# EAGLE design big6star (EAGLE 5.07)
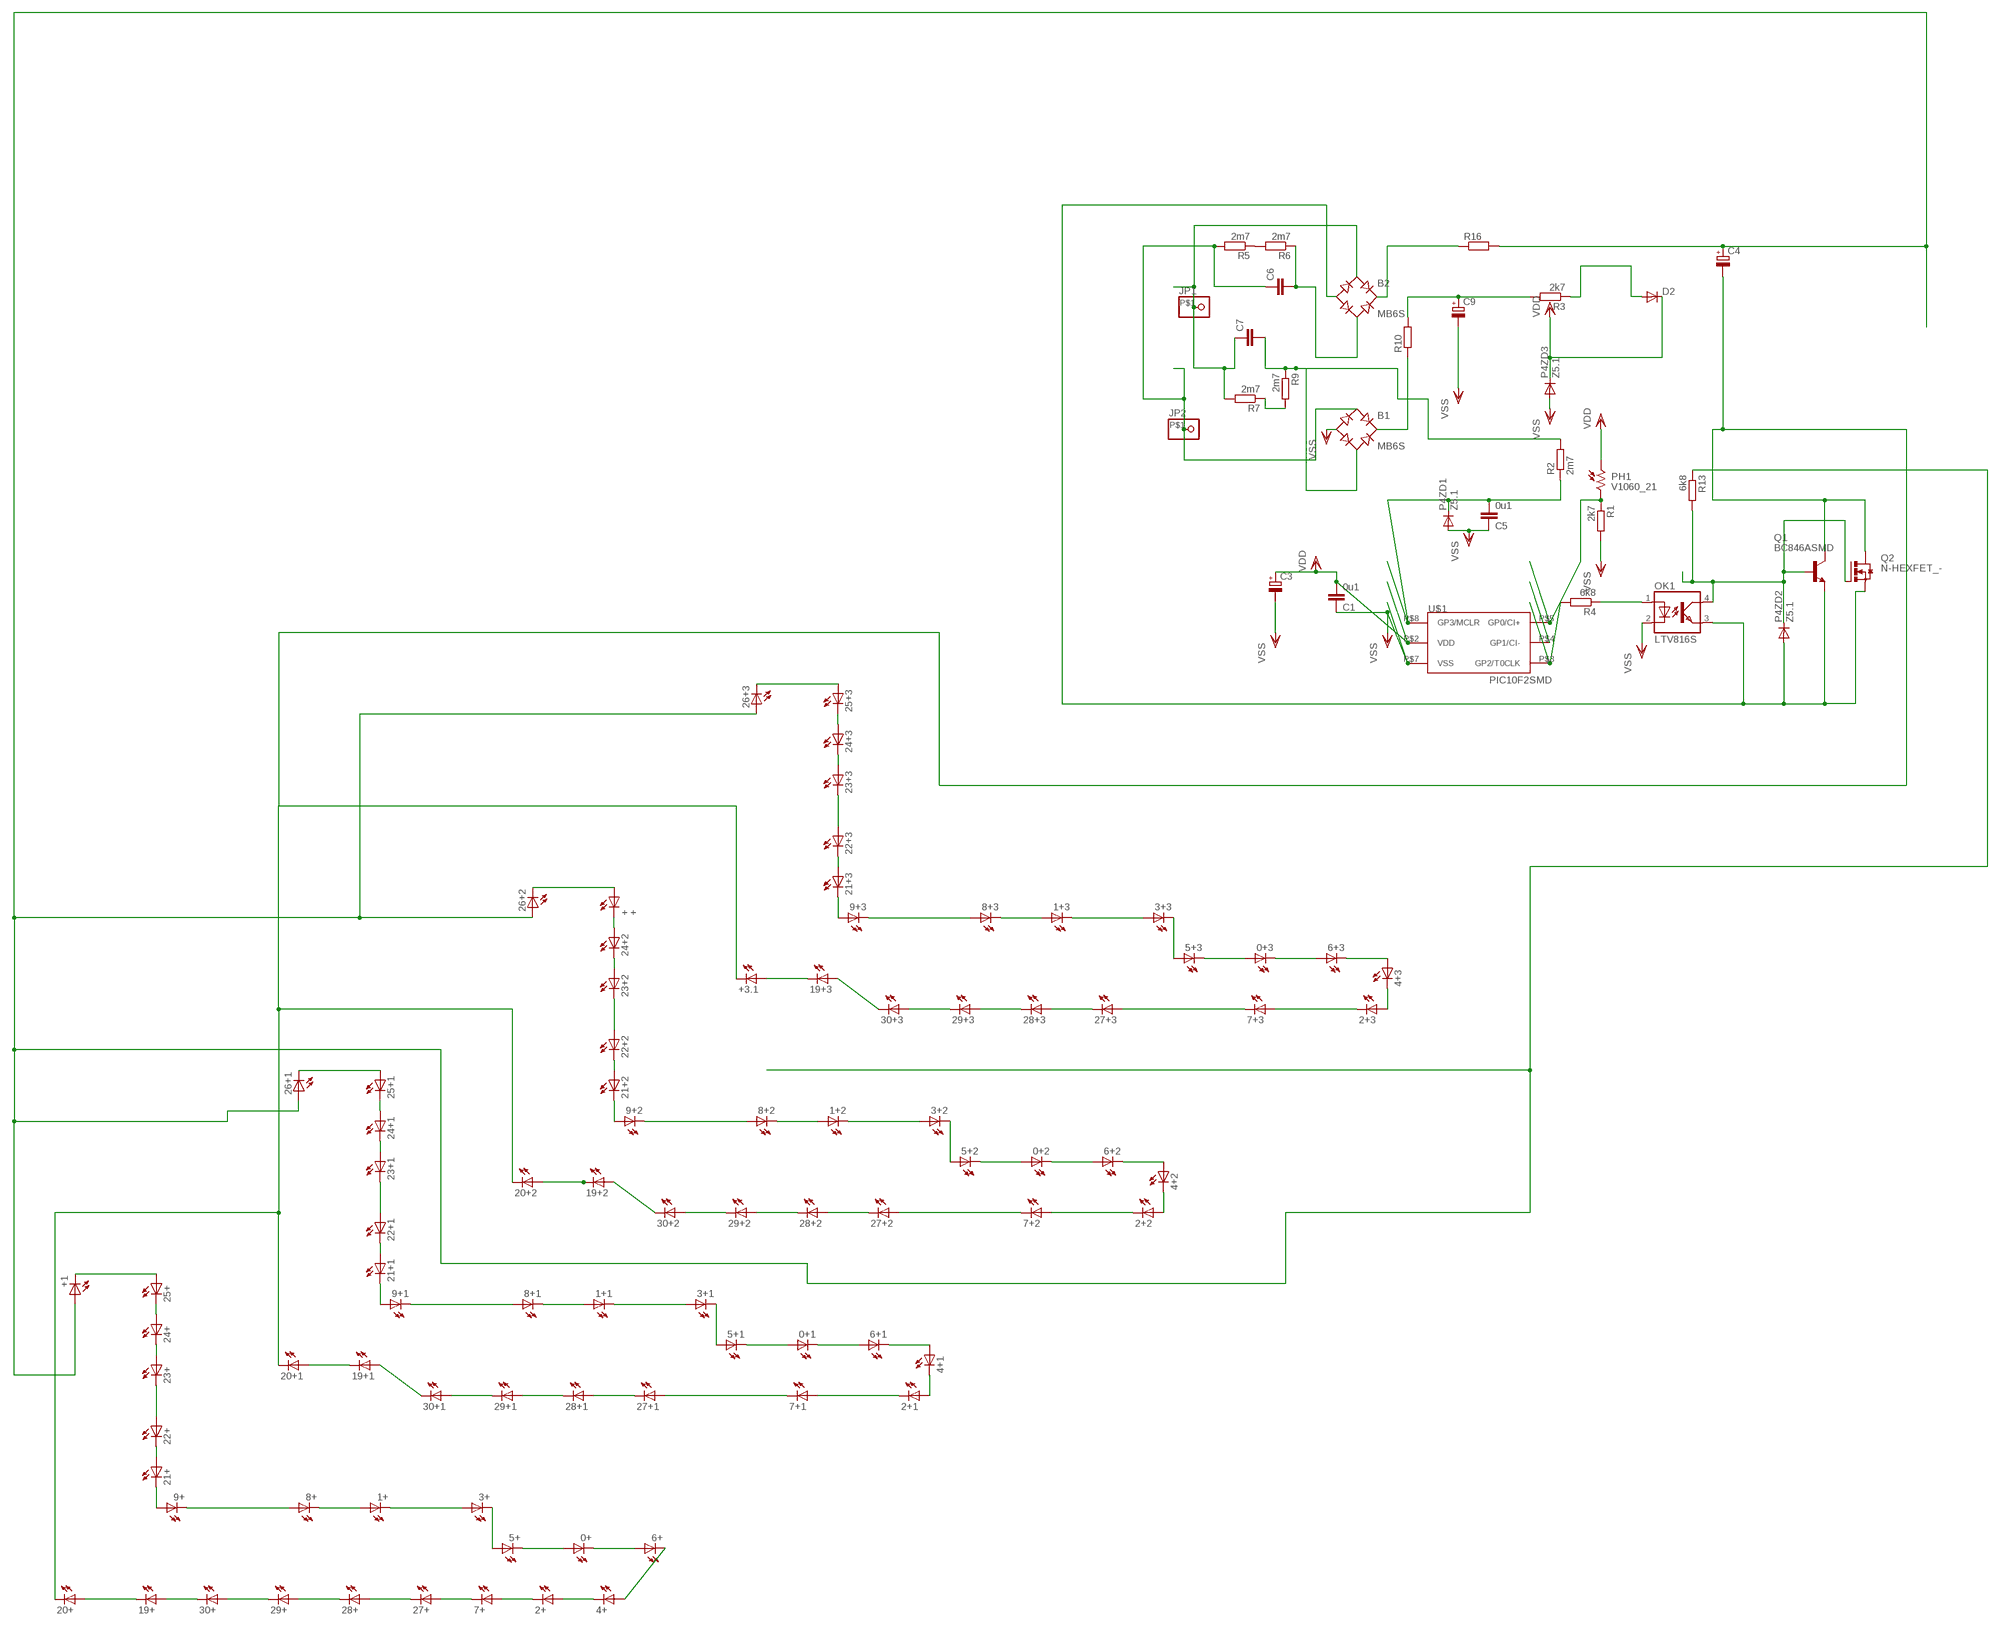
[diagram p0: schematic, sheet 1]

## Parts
0+  LED1210  [1210]
0+1  LED1210  [1210]
0+2  LED1210  [1210]
0+3  LED1210  [1210]
1+  LED1210  [1210]
1+1  LED1210  [1210]
1+2  LED1210  [1210]
1+3  LED1210  [1210]
2+  LED1210  [1210]
2+1  LED1210  [1210]
2+2  LED1210  [1210]
2+3  LED1210  [1210]
3+  LED1210  [1210]
3+1  LED1210  [1210]
3+2  LED1210  [1210]
3+3  LED1210  [1210]
4+  LED1210  [1210]
4+1  LED1210  [1210]
4+2  LED1210  [1210]
4+3  LED1210  [1210]
5+  LED1210  [1210]
5+1  LED1210  [1210]
5+2  LED1210  [1210]
5+3  LED1210  [1210]
6+  LED1210  [1210]
6+1  LED1210  [1210]
6+2  LED1210  [1210]
6+3  LED1210  [1210]
7+  LED1210  [1210]
7+1  LED1210  [1210]
7+2  LED1210  [1210]
7+3  LED1210  [1210]
8+  LED1210  [1210]
8+1  LED1210  [1210]
8+2  LED1210  [1210]
8+3  LED1210  [1210]
9+  LED1210  [1210]
9+1  LED1210  [1210]
9+2  LED1210  [1210]
9+3  LED1210  [1210]
19+  LED1210  [1210]
19+1  LED1210  [1210]
19+2  LED1210  [1210]
19+3  LED1210  [1210]
20+  LED1210  [1210]
20+1  LED1210  [1210]
20+2  LED1210  [1210]
21+  LED1210  [1210]
21+1  LED1210  [1210]
21+2  LED1210  [1210]
21+3  LED1210  [1210]
22+  LED1210  [1210]
22+1  LED1210  [1210]
22+2  LED1210  [1210]
22+3  LED1210  [1210]
23+  LED1210  [1210]
23+1  LED1210  [1210]
23+2  LED1210  [1210]
23+3  LED1210  [1210]
24+  LED1210  [1210]
24+1  LED1210  [1210]
24+2  LED1210  [1210]
24+3  LED1210  [1210]
25+  LED1210  [1210]
25+1  LED1210  [1210]
25+3  LED1210  [1210]
26+1  LED1210  [1210]
26+2  LED1210  [1210]
26+3  LED1210  [1210]
27+  LED1210  [1210]
27+1  LED1210  [1210]
27+2  LED1210  [1210]
27+3  LED1210  [1210]
28+  LED1210  [1210]
28+1  LED1210  [1210]
28+2  LED1210  [1210]
28+3  LED1210  [1210]
29+  LED1210  [1210]
29+1  LED1210  [1210]
29+2  LED1210  [1210]
29+3  LED1210  [1210]
30+  LED1210  [1210]
30+1  LED1210  [1210]
30+2  LED1210  [1210]
30+3  LED1210  [1210]
+  +  LED1210  [1210]
+1  LED1210  [1210]
+3.1  LED1210  [1210]
B1  MB6S  [SOIC-4]
B2  MB6S  [SOIC-4]
C1  0u1  C-EUC1206  [C1206]
C3  CPOL-EUD  [PANASONIC_D]
C4  CPOL-EUSANYO_SMD_F12  [SANYO-OSCON_SMD_F12]
C5  0u1  C-EUC1206  [C1206]
C6  C-EUSMD200  [SMD200]
C7  C-EUSMD100  [SMD100]
C9  CPOL-EUD  [PANASONIC_D]
D2  DIODE-MINIMELF  [MINIMELF]
JP1  PINHD-1X1SMD  [SMD1X1]
JP2  PINHD-1X1SMD  [SMD1X1]
OK1  LTV816S  [SMD4]
P4ZD1  Z5.1  DIODE-MINIMELF  [MINIMELF]
P4ZD2  Z5.1  DIODE-MINIMELF  [MINIMELF]
P4ZD3  Z5.1  DIODE-MINIMELF  [MINIMELF]
PH1  V1060_21  [TO-5_V10]
Q1  BC846ASMD  [SOT23]
Q2  N-HEXFET_-  [TO252]
R1  2k7  R-EU_R1206  [R1206]
R2  2m7  R-EU_R1206  [R1206]
R3  2k7  R-EU_R1206  [R1206]
R4  6k8  R-EU_R1206  [R1206]
R5  2m7  R-EU_R1210  [R1210]
R6  2m7  R-EU_R1210  [R1210]
R7  2m7  R-EU_R1210  [R1210]
R9  2m7  R-EU_R1210  [R1210]
R10  R-EU_SMD15  [SMDCARB15]
R13  6k8  R-EU_R1206  [R1206]
R16  R-EU_SMD15  [SMDCARB15]
U$1  PIC10F2SMD  [DIL8SMD]

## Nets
AC1: B1.~1(AC1) C6.P$1 JP2.P$1 R5.2
AC2: B2.~1(AC1) C7.P$1 JP1.P$1 R7.2
CBIG: B2.~2(AC2) C6.P$2 R6.1
CSMALL: B1.~2(AC2) C7.P$2 R2.2 R9.1
D+: 26+1.P$1(A) 26+2.P$1(A) 26+3.P$1(A) +1.P$1(A) C4.+ R13.1 R16.P$2
DR+: C9.+ R3.2 R10.P$2
MINUS: 20+1.P$2(C) 20+2.P$2(C) 20+.P$2(C) +3.1.P$2(C) C4.- Q1.3(C) Q2.3(D)
N$2: 19+.P$2(C) 20+.P$1(A)
N$4: 19+.P$1(A) 30+.P$2(C)
N$5: 19+1.P$1(A) 30+1.P$2(C)
N$6: 8+.P$1(A) 9+.P$2(C)
N$7: 29+.P$2(C) 30+.P$1(A)
N$8: 28+.P$2(C) 29+.P$1(A)
N$9: 27+.P$2(C) 28+.P$1(A)
N$10: 29+1.P$2(C) 30+1.P$1(A)
N$11: 28+1.P$2(C) 29+1.P$1(A)
N$12: 2+.P$2(C) 7+.P$1(A)
N$13: 7+.P$2(C) 27+.P$1(A)
N$14: 2+.P$1(A) 4+.P$2(C)
N$15: 4+.P$1(A) 6+.P$2(C)
N$16: 0+.P$2(C) 6+.P$1(A)
N$17: 0+.P$1(A) 5+.P$2(C)
N$18: 3+.P$2(C) 5+.P$1(A)
N$19: 1+.P$2(C) 3+.P$1(A)
N$20: 1+.P$1(A) 8+.P$2(C)
N$21: 27+1.P$2(C) 28+1.P$1(A)
N$22: 2+1.P$1(A) 4+1.P$2(C)
N$23: 9+.P$1(A) 21+.P$2(C)
N$24: 21+.P$1(A) 22+.P$2(C)
N$25: 22+.P$1(A) 23+.P$2(C)
N$26: 24+.P$1(A) 25+.P$2(C)
N$27: 25+.P$1(A) +1.P$2(C)
N$28: 23+.P$1(A) 24+.P$2(C)
N$29: 4+1.P$1(A) 6+1.P$2(C)
N$30: 0+1.P$2(C) 6+1.P$1(A)
N$31: 0+1.P$1(A) 5+1.P$2(C)
N$32: 3+1.P$2(C) 5+1.P$1(A)
N$33: 1+1.P$2(C) 3+1.P$1(A)
N$34: 1+1.P$1(A) 8+1.P$2(C)
N$35: 9+1.P$1(A) 21+1.P$2(C)
N$36: 21+1.P$1(A) 22+1.P$2(C)
N$37: 22+1.P$1(A) 23+1.P$2(C)
N$38: 25+1.P$1(A) 26+1.P$2(C)
N$39: 24+1.P$1(A) 25+1.P$2(C)
N$40: 23+1.P$1(A) 24+1.P$2(C)
N$41: 2+1.P$2(C) 7+1.P$1(A)
N$42: 7+1.P$2(C) 27+1.P$1(A)
N$43: 8+1.P$1(A) 9+1.P$2(C)
N$44: 19+1.P$2(C) 20+1.P$1(A)
N$45: 19+2.P$1(A) 30+2.P$2(C)
N$46: 29+2.P$2(C) 30+2.P$1(A)
N$47: 28+2.P$2(C) 29+2.P$1(A)
N$48: 27+2.P$2(C) 28+2.P$1(A)
N$49: 2+2.P$1(A) 4+2.P$2(C)
N$50: 4+2.P$1(A) 6+2.P$2(C)
N$51: 0+2.P$2(C) 6+2.P$1(A)
N$52: 0+2.P$1(A) 5+2.P$2(C)
N$53: 3+2.P$2(C) 5+2.P$1(A)
N$54: 1+2.P$2(C) 3+2.P$1(A)
N$55: 1+2.P$1(A) 8+2.P$2(C)
N$56: 9+2.P$1(A) 21+2.P$2(C)
N$57: 21+2.P$1(A) 22+2.P$2(C)
N$58: 22+2.P$1(A) 23+2.P$2(C)
N$59: 26+2.P$2(C) +.P$1(A)
N$60: 24+2.P$1(A) +.P$2(C)
N$61: 23+2.P$1(A) 24+2.P$2(C)
N$62: 2+2.P$2(C) 7+2.P$1(A)
N$63: 7+2.P$2(C) 27+2.P$1(A)
N$64: 8+2.P$1(A) 9+2.P$2(C)
N$65: 19+2.P$2(C) 20+2.P$1(A)
N$66: 19+3.P$1(A) 30+3.P$2(C)
N$67: 29+3.P$2(C) 30+3.P$1(A)
N$68: 28+3.P$2(C) 29+3.P$1(A)
N$69: 27+3.P$2(C) 28+3.P$1(A)
N$70: 2+3.P$1(A) 4+3.P$2(C)
N$71: 4+3.P$1(A) 6+3.P$2(C)
N$72: 0+3.P$2(C) 6+3.P$1(A)
N$73: 0+3.P$1(A) 5+3.P$2(C)
N$74: 3+3.P$2(C) 5+3.P$1(A)
N$75: 1+3.P$2(C) 3+3.P$1(A)
N$76: 1+3.P$1(A) 8+3.P$2(C)
N$77: 9+3.P$1(A) 21+3.P$2(C)
N$78: 21+3.P$1(A) 22+3.P$2(C)
N$79: 22+3.P$1(A) 23+3.P$2(C)
N$80: 25+3.P$1(A) 26+3.P$2(C)
N$81: 24+3.P$1(A) 25+3.P$2(C)
N$82: 23+3.P$1(A) 24+3.P$2(C)
N$83: 2+3.P$2(C) 7+3.P$1(A)
N$84: 7+3.P$2(C) 27+3.P$1(A)
N$85: 8+3.P$1(A) 9+3.P$2(C)
N$86: C5.2 P4ZD1.C R2.1 U$1.P$8(GP3/MCLR)
N$87: OK1.1(A) R4.1
N$88: PH1.2 R1.1 U$1.P$5(GP0/CI+)
N$89: R5.1 R6.2
N$90: R7.1 R9.2
N$91: B2.+ R16.P$1
N$92: D2.A R3.1
N$93: B2.- OK1.3(EMIT) P4ZD2.A Q1.2(E) Q2.2(S)
N$94: OK1.4(COL) P4ZD2.C Q1.1(B) Q2.1(G) R13.2
N$95: R4.2 U$1.P$3(GP2/T0CLK)
N$97: 19+3.P$2(C) +3.1.P$1(A)
N$102: U$1.P$4(GP1/CI-)
RECDR+: B1.+ R10.P$1
VDD: C1.2 C3.+ D2.C P4ZD3.C PH1.1 U$1.P$2(VDD)
VSS: B1.- C1.1 C3.- C5.1 C9.- OK1.2(C) P4ZD1.A P4ZD3.A R1.2 U$1.P$7(VSS)

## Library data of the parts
0+ 0+1-0+3 1+ 1+1-1+3 2+ 2+1-2+3 3+ 3+1-3+3 4+ 4+1-4+3 5+ 5+1-5+3 6+ 6+1-6+3 7+ 7+1-7+3 8+ 8+1-8+3 9+ 9+1-9+3 19+ 19+1-19+3 20+ 20+1 20+2 21+ 21+1-21+3 22+ 22+1-22+3 23+ 23+1-23+3 24+ 24+1-24+3 25+ 25+1 25+3 26+1-26+3 27+ 27+1-27+3 28+ 28+1-28+3 29+ 29+1-29+3 30+ 30+1-30+3 + +1 +3.1 = led(2):LED: LED
B1 B2 = rectifier:MB*S: Bridge Rectifier Source: http://www.fairchildsemi.com/ds/MB/MB6S.pdf
C1 C5-C7 = rcl:C-EU: CAPACITOR, European symbol
C3 C4 C9 = rcl-2:CPOL-EU: POLARIZED CAPACITOR, European symbol
D2 P4ZD1-P4ZD3 = diode:DIODE-: DIODE
JP1 JP2 = pinhead:PINHD-1X1: PIN HEADER
OK1 = optocoupler:LTV816: OPTO COUPLER Source: LITEON, LTV816.pdf
PH1 = photo-elements:?1060*: Sensor Street Light control
Q1 = transistor-npn:BC846*: NPN Transistor
Q2 = transistor-power:N-HEXFET_?-*: HEXFET® Power MOSFET
R1-R7 R9 R13 = rcl-2:R-EU_: RESISTOR, European symbol
R10 R16 = rcl:R-EU_: RESISTOR, European symbol
U$1 = microchip-5:PIC10F2*: uPC nW 0,25/0,5k Program Flash memory Comparator

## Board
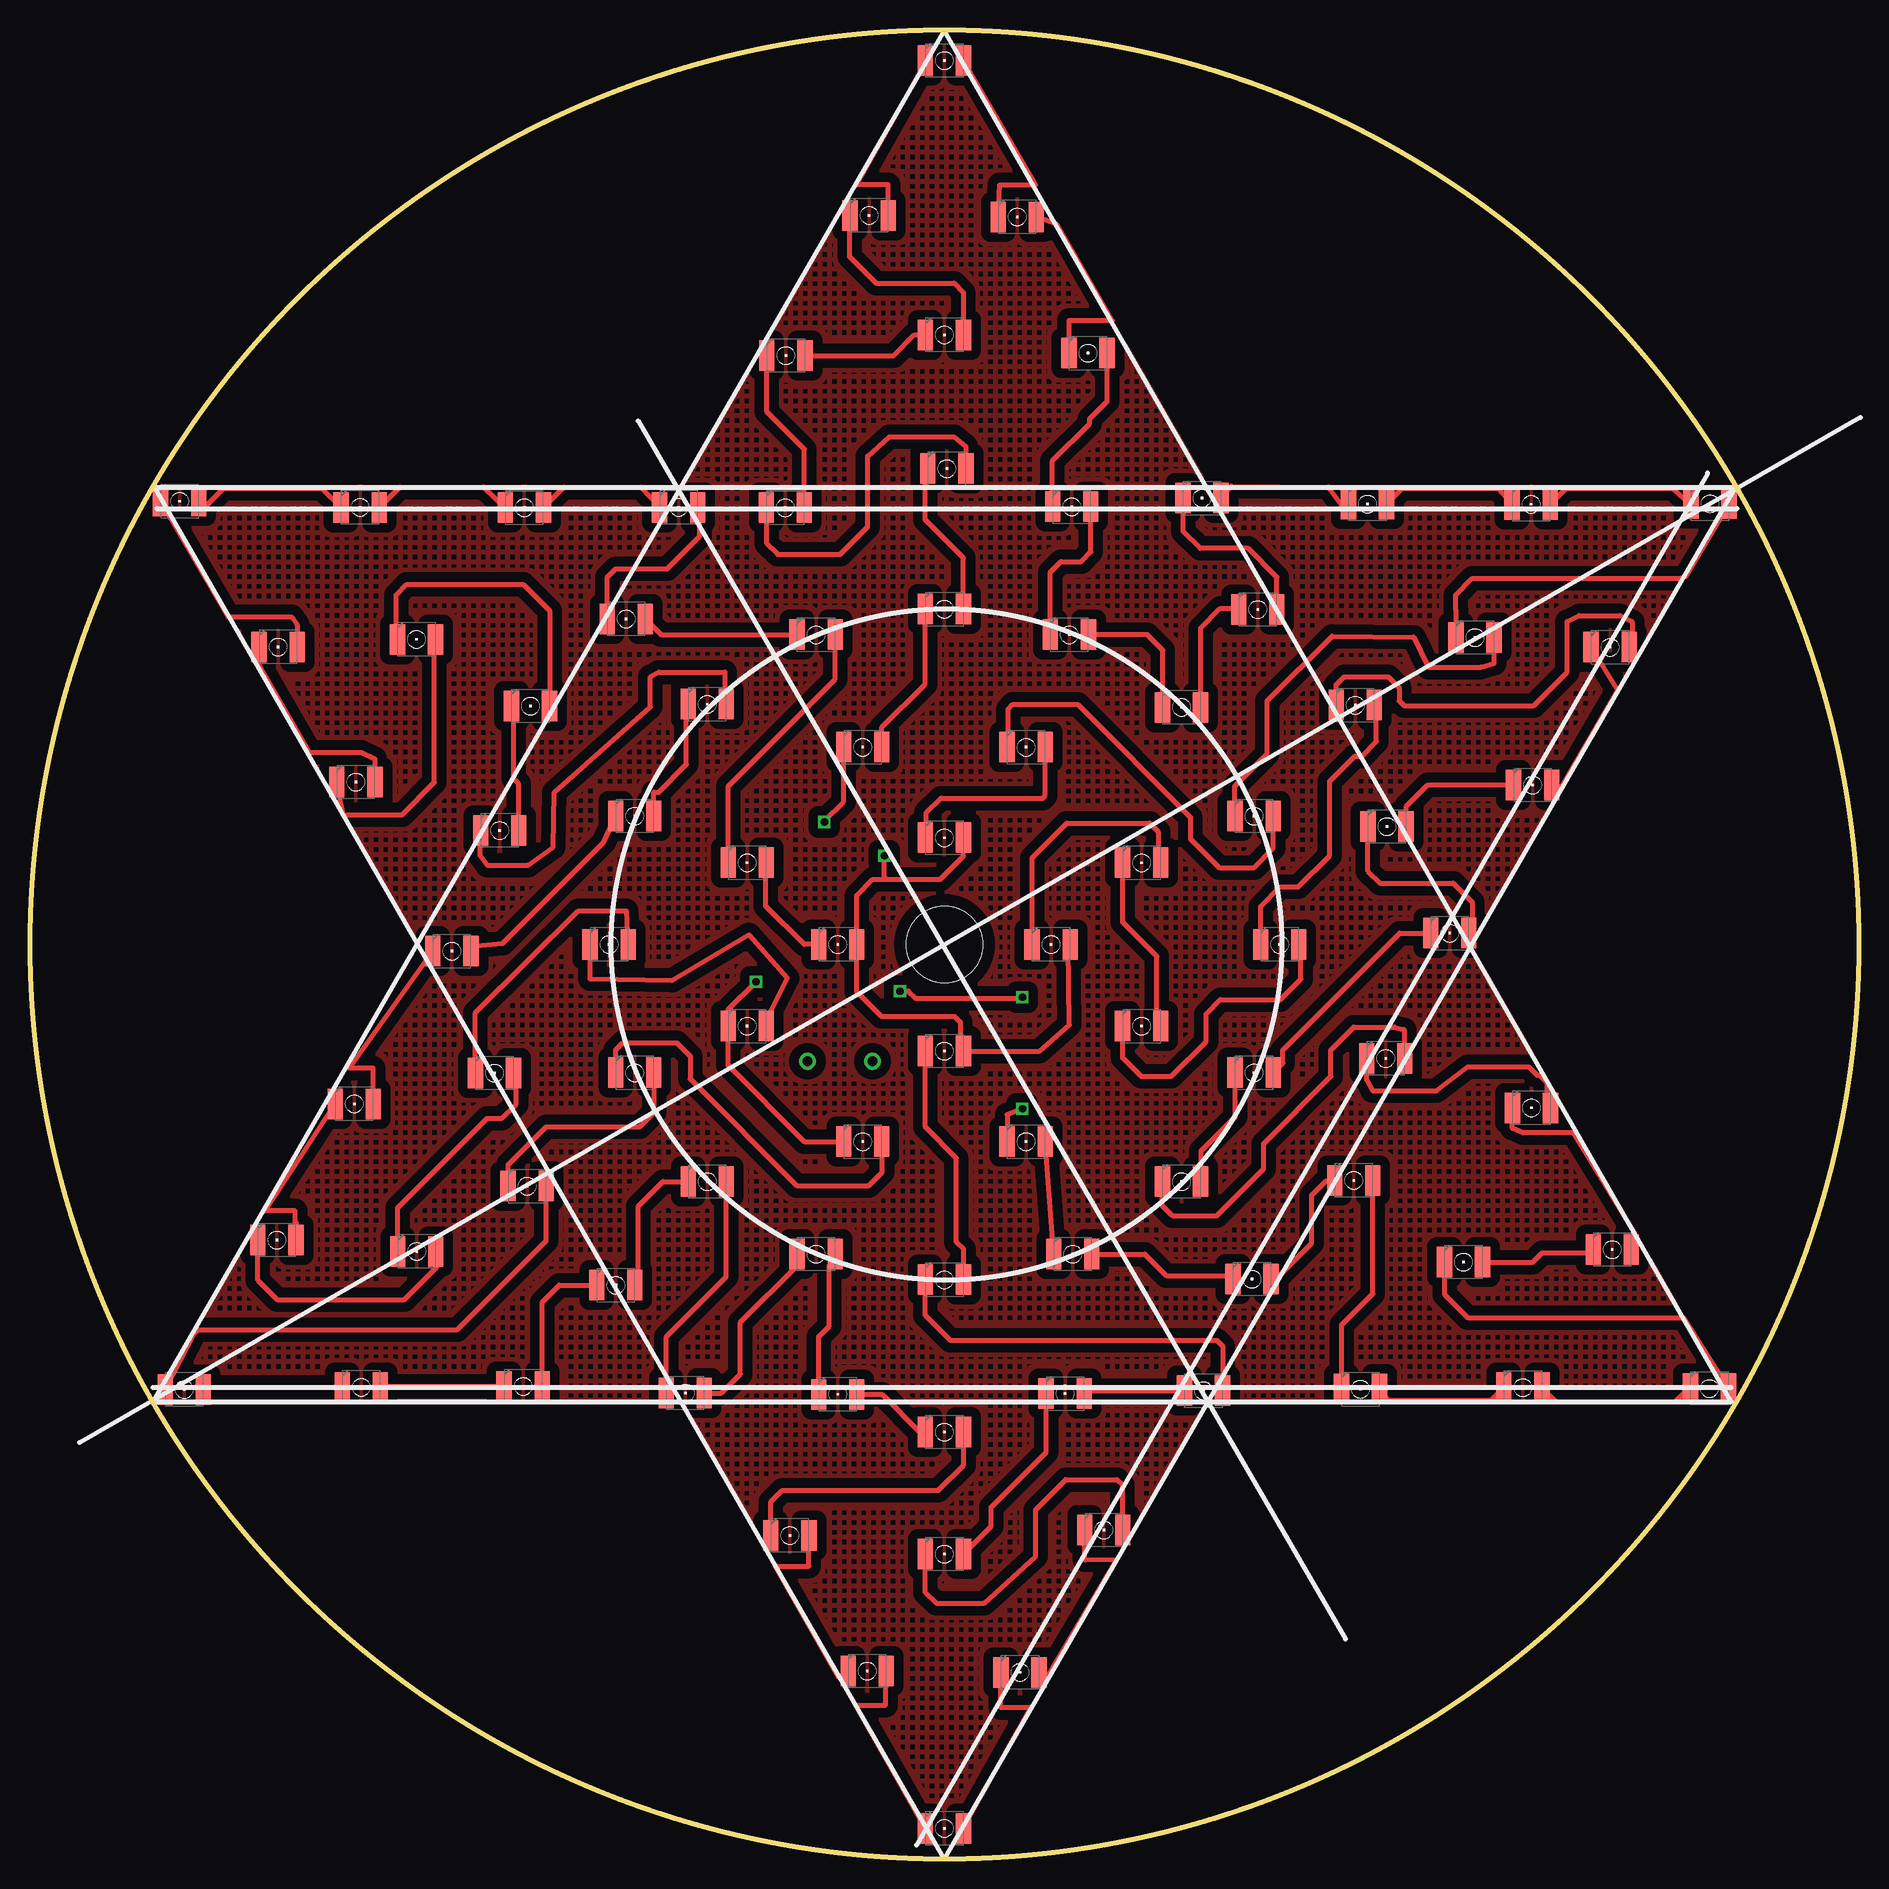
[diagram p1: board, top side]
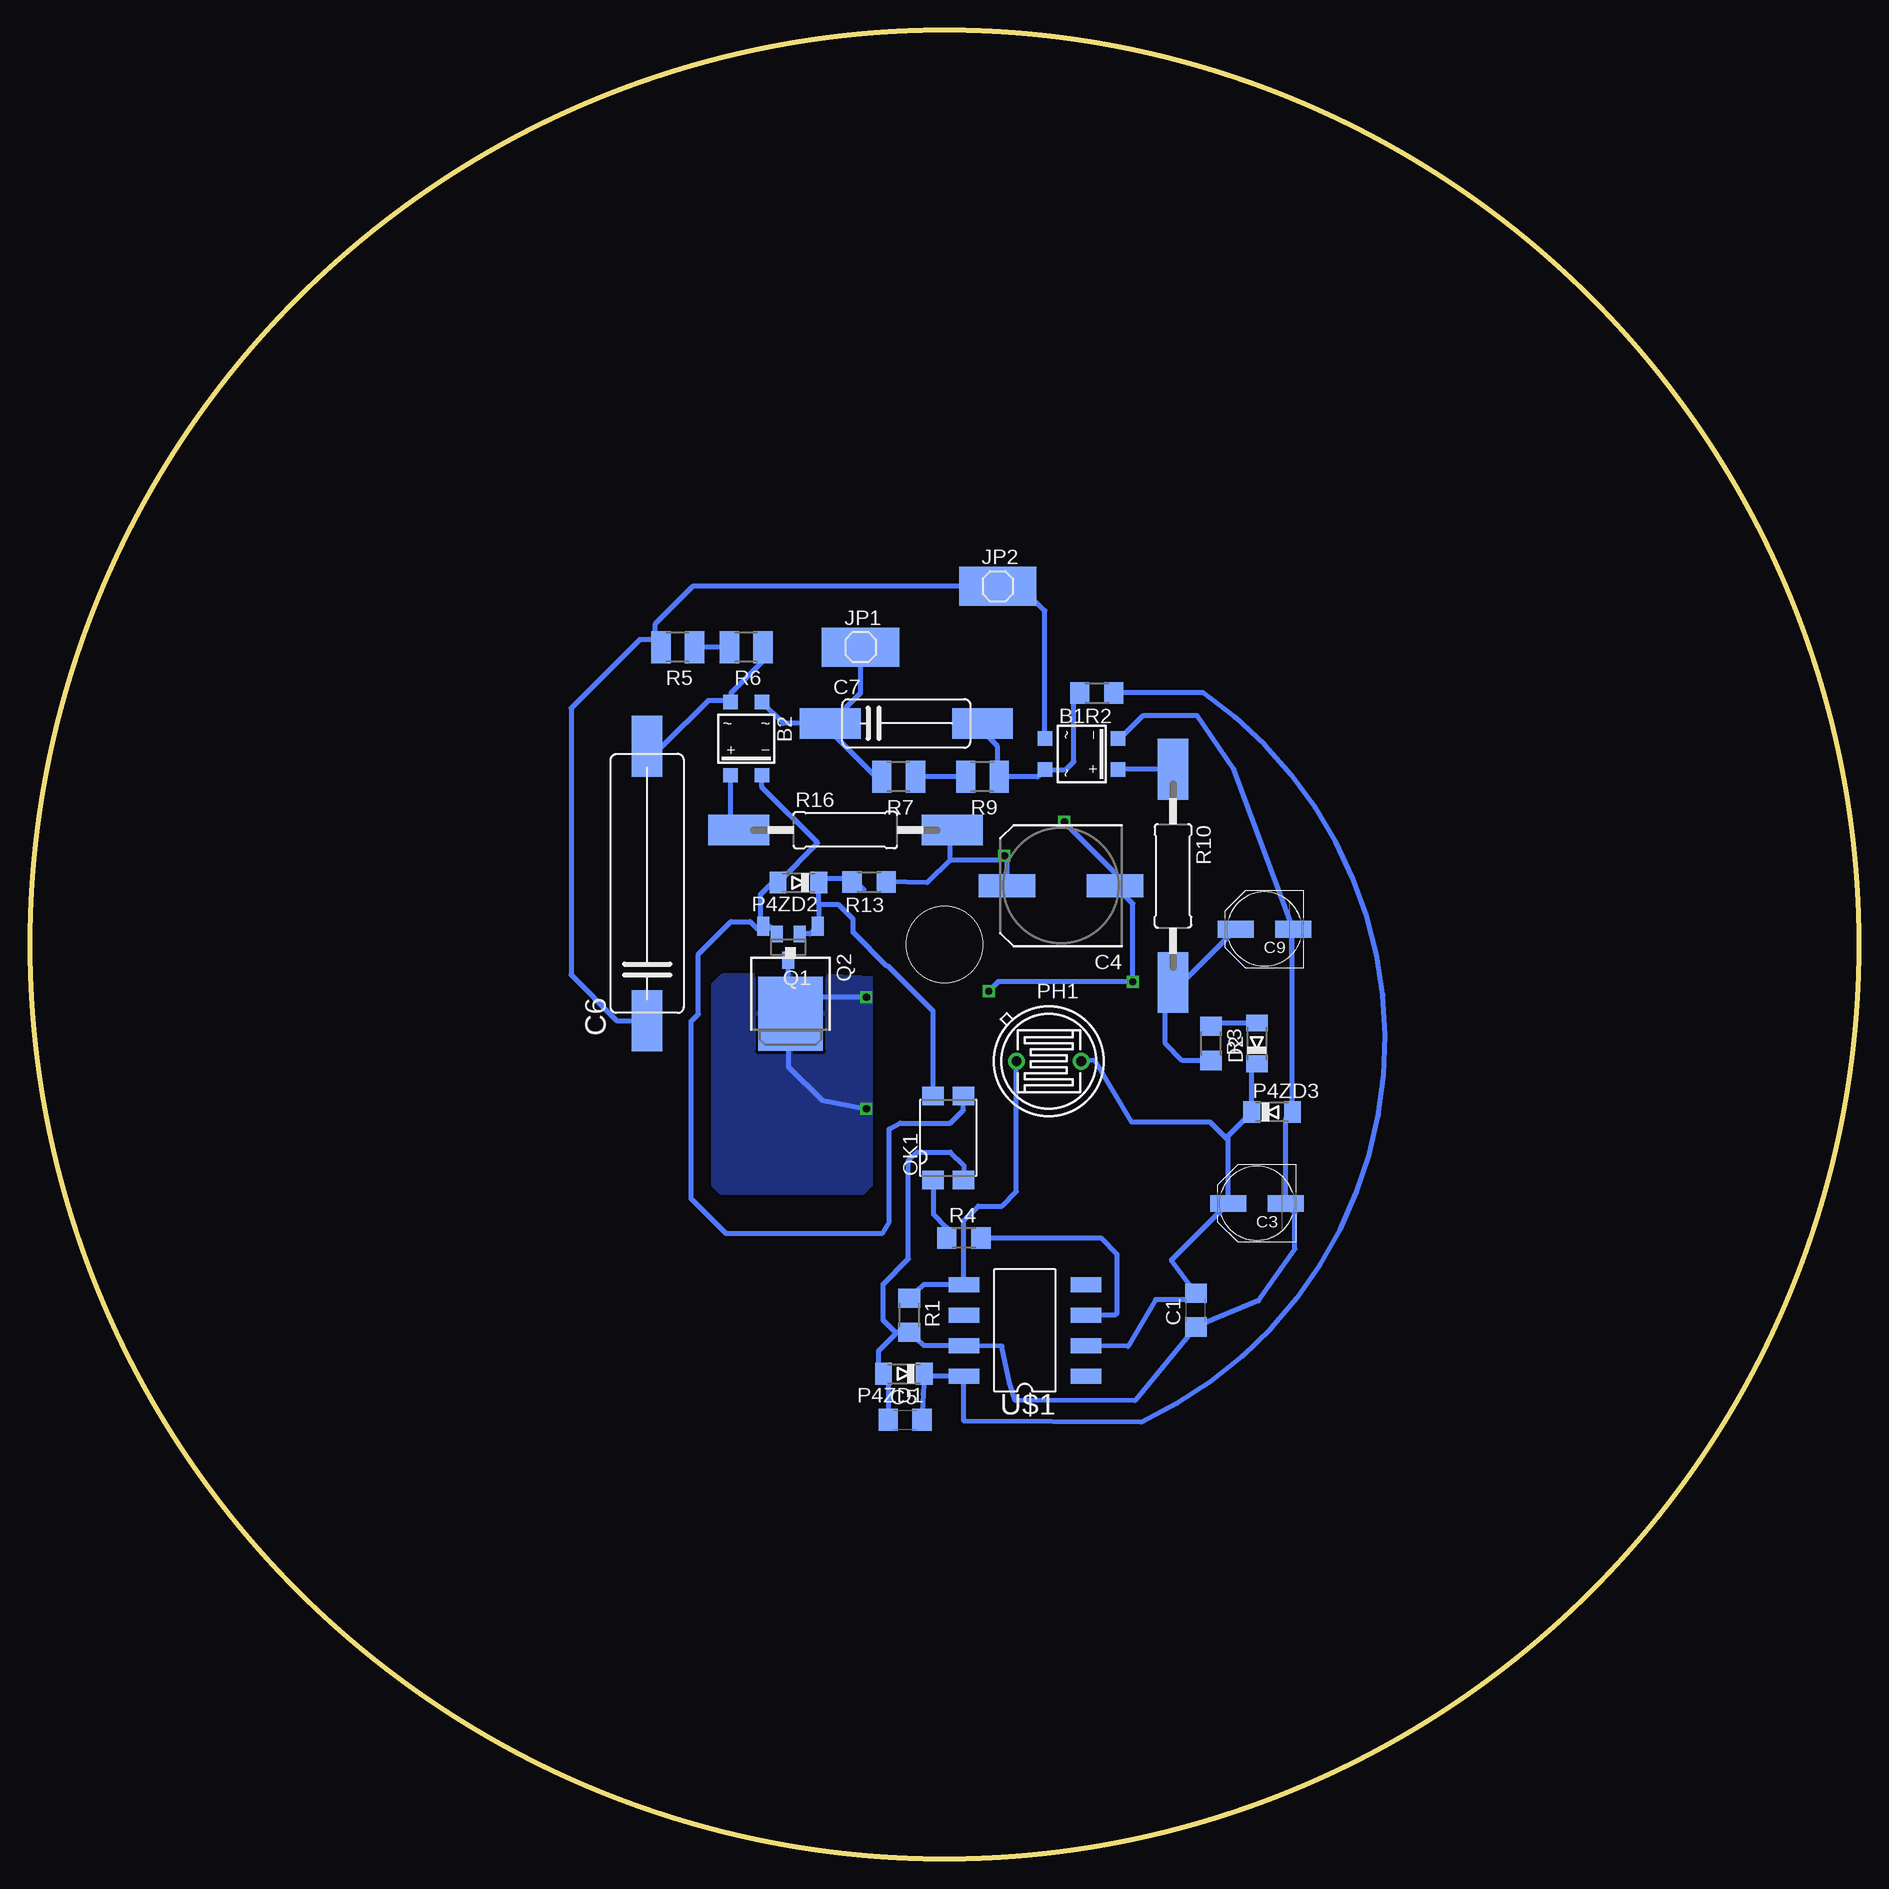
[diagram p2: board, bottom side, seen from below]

Size 152.4 x 152.4 mm. Coordinates in mm from the lower left corner, seen from the top.
Outline: circle at 76.2,76.2 radius 76.2
Copper layers (1*16): Top 0.035mm / dielectric 1.5mm / Bottom 0.035mm
Design rules "default": minimum track width 10mil, minimum drill 24mil, track to track 8mil, track to pad 8mil, pad to pad 8mil, via to via 8mil, smd to smd 8mil, copper to edge 40mil, drill to drill 8mil, minimum pad ring 10mil, minimum via ring 8mil, stop-mask expansion 4mil, vias tented up to drill 0mil, thermal gap 10mil
Holes 6.35 mm at 76.2,76.2

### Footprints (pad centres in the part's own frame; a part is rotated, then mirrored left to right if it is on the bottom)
1210 = smd 1.27 x 2.54: P$1 1.587,0; P$2 -1.587,0
SOIC-4 = smd 1.2 x 1.2: + 1.3,3.05; - -1.3,3.05; ~1 -1.3,-3.05; ~2 1.3,-3.05
C1206 = smd 1.6 x 1.8: 1 -1.4,0; 2 1.4,0
PANASONIC_D = smd 3 x 1.4: + 2.4,0; - -2.4,0
SANYO-OSCON_SMD_F12 = smd 4.7 x 1.9: + 4.5,0; - -4.5,0
SMD200 = smd 5.08 x 2.54: P$1 -10.16,0; P$2 12.7,0
SMD100 = smd 5.08 x 2.54: P$1 -6.35,0; P$2 6.35,0
MINIMELF = smd 1.4 x 1.8: A 1.7,0; C -1.7,0
SMD1X1 = smd 6.452 x 3.251: P$1 0,0
SMD4 = smd 1.78 x 1.55: 1 -1.27,-3.5; 2 1.27,-3.5; 3 1.27,3.5; 4 -1.27,3.5
TO-5_V10 = drill 0.8 pad 1.4 round: 1 -2.7,0; 2 2.7,0
SOT23 = smd 1 x 1.4: 1 -0.95,-1.1; 2 0.95,-1.1; 3 0,1.1
TO252 = smd 1 x 1.6: 1 -2.28,-3.53; 2 2.28,-3.53 | smd 5.4 x 6.2: 3 0,3.77
R1206 = smd 1.6 x 1.803: 1 -1.422,0; 2 1.422,0
R1210 = smd 1.6 x 2.7: 1 -1.4,0; 2 1.4,0
SMDCARB15 = smd 5.08 x 2.54: P$1 -8.89,0; P$2 8.89,0
DIL8SMD = smd 1.27 x 2.54: P$1 -3.81,-5.08; P$2 -1.27,-5.08; P$3 1.27,-5.08; P$4 3.81,-5.08; P$5 3.81,5.08; P$6 1.27,5.08; P$7 -1.27,5.08; P$8 -3.81,5.08

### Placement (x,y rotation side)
0+  67.31,38.71 0 top
0+1  112.98,66.7 0 top
0+2  86.82,112.67 0 top
0+3  41.71,96.06 0 top
1+  69.77,15.65 0 top
1+1  118.31,77.14 0 top
1+2  102.31,104.11 0 top
1+3  20.68,100.99 0 top
2+  56.44,56.44 0 top
2+1  119.46,49.73 0 top
2+2  76.2,149.86 0 top
2+3  50.39,86.89 0 top
3+  63.32,26.95 0 top
3+1  102.01,65.51 0 top
3+2  95.96,95.96 0 top
3+3  27.15,89.74 0 top
4+  54.61,38.81 0 top
4+1  131.85,50.77 0 top
4+2  82.27,136.83 0 top
4+3  56.44,96.22 0 top
5+  76.2,35.56 0 top
5+1  95.96,56.44 0 top
5+2  86.61,102.01 0 top
5+3  32.21,101.63 0 top
6+  65.51,50.39 0 top
6+1  125.12,62.59 0 top
6+2  88.16,125.48 0 top
6+3  39.14,85.7 0 top
7+  48.82,47.8 0 top
7+1  139.95,39.19 0 top
7+2  69.93,136.96 0 top
7+3  35.15,75.64 0 top
8+  76.2,2.54 0 top
8+1  113.08,86.03 0 top
8+2  97.66,113.39 0 top
8+3  12.47,113.13 0 top
9+  82.5,15.54 0 top
9+1  125.22,89.48 0 top
9+2  111.46,112.9 0 top
9+3  27.51,112.62 0 top
19+  50.39,65.51 0 top
19+1  86.89,50.39 0 top
19+2  76.2,104.14 0 top
19+3  48.26,76.2 0 top
20+  69.39,59.77 0 top
20+1  83.01,59.77 0 top
20+2  69.39,92.63 0 top
21+  89.48,27.41 0 top
21+1  131.67,100.97 0 top
21+2  125.09,112.88 0 top
21+3  41.2,112.6 0 top
22+  76.2,25.4 0 top
22+1  110.44,96.14 0 top
22+2  140,112.93 0 top
22+3  54.05,112.62 0 top
23+  86.26,38.76 0 top
23+1  104.14,76.2 0 top
23+2  120.42,101.78 0 top
23+3  49.68,103.33 0 top
24+  97.79,39.01 0 top
24+1  92.63,69.39 0 top
24+2  102.01,86.89 0 top
24+3  65.51,102.01 0 top
25+  76.2,48.26 0 top
25+1  92.63,83.01 0 top
25+3  59.77,83.01 0 top
26+1  85.09,76.2 0 top
26+2  76.2,85.09 0 top
26+3  67.31,76.2 0 top
27+  41.1,39.37 0 top
27+1  124.41,39.27 0 top
27+2  76.2,127 0 top
27+3  27.03,62.92 0 top
28+  27.61,39.29 0 top
28+1  110.87,39.14 0 top
28+2  62.99,125.27 0 top
28+3  20.57,51.56 0 top
29+  12.85,39.12 0 top
29+1  110.31,56.54 0 top
29+2  62.94,112.6 0 top
29+3  32.23,50.62 0 top
30+  41.43,56.06 0 top
30+1  101.83,48.31 0 top
30+2  76.4,115.85 0 top
30+3  38.71,65.48 0 top
+  83.01,92.63 0 top
+1  76.2,67.31 0 top
+3.1  59.77,69.39 0 top
B1  64.77,92.08 270 bottom
B2  92.71,93.34 180 bottom
C1  55.24,45.72 90 bottom
C3  50.16,54.61 180 bottom
C4  66.49,81.09 180 bottom
C5  79.47,36.59 0 bottom
C6  100.97,80.01 90 bottom
C7  79.38,94.61 0 bottom
C9  49.53,77.47 180 bottom
D2  50.16,67.94 90 bottom
JP1  83.19,100.97 0 bottom
JP2  71.75,106.05 0 bottom
OK1  75.88,60.08 0 bottom
P4ZD1  79.57,40.42 180 bottom
P4ZD2  88.37,81.36 180 bottom
P4ZD3  48.9,62.23 0 bottom
PH1  67.5,66.46 180 bottom
Q1  89.2,75.97 180 bottom
Q2  89.03,74.19 180 bottom
R1  79.12,45.3 270 bottom
R2  63.5,97.16 180 bottom
R3  53.98,67.94 270 bottom
R4  74.57,51.74 0 bottom
R5  98.42,100.97 180 bottom
R6  92.71,100.97 180 bottom
R7  80.01,90.17 180 bottom
R9  73.03,90.17 180 bottom
R10  57.15,81.92 270 bottom
R13  82.48,81.41 180 bottom
R16  84.45,85.72 0 bottom
U$1  69.5,44.03 90 bottom

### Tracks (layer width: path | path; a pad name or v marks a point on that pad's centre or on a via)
AC1
  Bottom 0.406: B1.~1 67.82,104.02 69.85,106.05 JP2.P$1 97.16,106.05 100.33,102.87 100.33,101.6 | 100.33,101.6 100.33,101.47 R5.2 | C6.P$1 103.5,69.85 107.31,73.66 107.31,95.89 101.6,101.6 100.33,101.6
AC2
  Bottom 0.406: R7.2 81.92,90.17 86.36,94.61 C7.P$1 | JP1.P$1 83.19,97.16 C7.P$1 | C7.P$1 89.63,94.61 B2.~1
CBIG
  Bottom 0.406: R6.1 91.31,99.83 93.98,97.16 93.98,96.42 B2.~2 94.14,96.52 95.89,96.52 99.69,92.71 C6.P$2
CSMALL
  Bottom 0.406: R2.2 65.41,96.67 65.41,91.44 66.07,90.78 B1.~2 68.42,90.17 R9.1 71.75,90.3 71.75,92.71 73.03,93.98 C7.P$2
D+  (via drill 0.6)
  Top 0.406: 26+1.P$1 86.51,76.03 86.61,69.5 84.12,67.31 +1.P$1 77.52,67.58 77.52,69.72 77.04,70.21 70.94,70.21 68.9,72.25 26+3.P$1 68.89,76.21 68.89,80.26 70.23,81.61 71.4,81.61 | 26+2.P$1 77.79,83.55 75.84,81.61 71.4,81.61 | v71.2,83.6 71.2,81.81 71.4,81.61
  Bottom 0.406: R13.1 77.64,81.36 75.7,83.2 | 75.7,83.2 75.7,85 76.1,85.4 75.89,85.4 R16.P$2 | C4.+ 70.99,83.39 v71.2,83.6 71.6,83.2 75.7,83.2
DR+
  Bottom 0.406: R3.2 56.36,66.52 57.78,67.94 57.78,72.39 R10.P$2 56.38,73.03 C9.+
MINUS  (via drill 0.6)
  Top 0.406: 20+.P$2 64.54,59.77 58.18,66.13 +3.1.P$2 58.18,70.78 v60.5,73.1 | v66.2,86.4 66.2,86.5 67.8,88.1 20+2.P$2 | v72.5,72.3 73.2,72.3 73.8,71.7 82.6,71.7 v82.7,71.8 | 20+1.P$2 81.42,62.02 v82.7,62.5
  Bottom 0.406: v66.2,86.4 61.99,82.19 C4.- 60.5,79.61 v60.5,73.1 71.7,73.1 v72.5,72.3 | v82.7,71.8 87.65,71.8 | 87.65,71.8 Q2.3 89.2,70.25 89.2,66 86.4,63.2 v82.7,62.5 | 87.65,71.8 89,71.8 89.2,72 Q1.3
  pour Bottom: 86.87,73.58 94.67,73.58 95.45,72.8 95.45,56.21 94.79,55.55 86.77,55.55 82.98,55.55 82.32,56.21 82.32,73.36
N$2
  Top 0.406: 19+.P$2 48.81,67.41 49.4,68 53.9,68 55,66.9 55,65 63.9,56.1 69.9,56.1 71,57.2 71,59.75 20+.P$1
N$3
  pour Top (isolate 0.813, hatched): 32.44,76 10.41,38.1 54.2,38.15 76.2,0 98.15,38.13 141.88,38 120.02,76.05 142.16,114.33 98.15,114.3 76.2,152.4 54.23,114.3 10.49,114.3
N$4
  Top 0.406: 30+.P$2 39.84,57.84 43,61 50.8,61 52,62.2 52,65.49 19+.P$1
N$5
  Top 0.406: 19+1.P$1 92.91,50.39 94.7,48.6 99.95,48.6 30+1.P$2
N$6
  Top 0.406: 9+.P$2 80.9,12.6 83.4,12.6 8+.P$1
N$7
  Top 0.406: 29+.P$2 13.7,43.8 14,44.1 35.6,44.1 43,51.5 43,55.5 43.02,55.52 30+.P$1
N$8
  Top 0.406: 28+.P$2 14.62,39.29 29+.P$1
N$9
  Top 0.406: 27+.P$2 29.27,39.37 28+.P$1
N$10
  Top 0.406: 30+1.P$1 103.81,48.31 106.8,51.3 106.8,55.3 108,56.5 108.68,56.5 29+1.P$2
N$11
  Top 0.406: 29+1.P$1 111.9,47.1 109.3,44.5 109.3,39.9 109.2,39.8 109.2,39.23 28+1.P$2
N$12
  Top 0.406: 2+.P$2 52.74,56.44 50.7,54.4 50.7,48.1 7+.P$1
N$13
  Top 0.406: 7+.P$2 44.1,47.8 42.7,46.4 42.7,39.38 27+.P$1
N$14
  Top 0.406: 4+.P$2 53.02,43.52 58,48.5 58,56.41 2+.P$1
N$15
  Top 0.406: 6+.P$2 63.92,49.42 59.2,44.7 59.2,40.4 57.6,38.8 4+.P$1
N$16
  Top 0.406: 0+.P$2 65.72,43.52 66.6,44.4 66.6,49.4 67.1,49.9 67.1,49.8 | 67.1,49.8 66.9,49.6 | 67.1,49.8 67.2,49.9 67.2,50.29 6+.P$1
N$17
  Top 0.406: 5+.P$2 74.14,35.56 71,38.7 0+.P$1
N$18
  Top 0.406: 3+.P$2 61.73,29.73 62.7,30.7 75.7,30.7 77.8,32.8 77.8,35.55 5+.P$1
N$19
  Top 0.406: 1+.P$2 67.4,15.1 62.1,24.4 64.9,24.4 64.9,26.3 3+.P$1
N$20
  Top 0.406: 8+.P$2 68.8,12.8 71.3,12.8 1+.P$1
N$21
  Top 0.406: 28+1.P$1 113.2,38.2 121.75,38.2 27+1.P$2
N$22
  Top 0.406: 2+1.P$1 125.23,49.73 126,50.5 129.99,50.5 4+1.P$2
N$23
  Top 0.406: 21+.P$2 87.9,24.9 90.5,24.9 84.9,15.4 9+.P$1
N$24
  Top 0.406: 22+.P$2 74.61,22.19 75.5,21.3 79.5,21.3 83.8,25.2 83.8,29.1 86.3,31.6 90.6,31.6 91,31.2 91,27.48 21+.P$1
N$25
  Top 0.406: 23+.P$2 84.67,33.87 80.1,29.3 80.1,27.71 22+.P$1
N$26
  Top 0.406: 24+.P$1 99.38,42.72 98.9,43.2 76.7,43.2 74.6,45.3 74.6,48.25 25+.P$2
N$27
  Top 0.406: +1.P$2 74.61,60.99 77.2,58.4 77.2,51.4 77.8,50.8 77.8,48.27 25+.P$1
N$28
  Top 0.406: 24+.P$2 88.1,39.01 23+.P$1
N$29
  Top 0.406: 6+1.P$2 123.53,60.87 124.4,60.5 128.6,60.5 130.5,57.4 133.7,52.2 4+1.P$1
N$30
  Top 0.406: 0+1.P$2 111.39,64.91 111.9,64 117.2,64 119.8,66 124.9,66 125.6,65.3 125.8,65.3 126.4,64.7 126.4,62.89 6+1.P$1
N$31
  Top 0.406: 5+1.P$2 94.37,54.43 95.2,53.6 98.9,53.6 102.8,57.5 102.8,59.6 108.4,65.2 108.4,67.4 110.3,69.3 113.7,69.3 114.5,69.1 114.5,66.77 0+1.P$1
N$32
  Top 0.406: 3+1.P$2 100.42,61.82 97.6,59 97.6,56.49 5+1.P$1
N$33
  Top 0.406: 1+1.P$2 114.13,77.14 104.4,67.4 104.4,66.31 3+1.P$1
N$34
  Top 0.406: 8+1.P$2 111.49,82.31 112.5,81.3 118.6,81.3 120.2,79.7 120.2,77.44 1+1.P$1
N$35
  Top 0.406: 21+1.P$2 132.3,97.4 127.6,89.3 9+1.P$1
N$36
  Top 0.406: 22+1.P$2 108.85,97.85 109.5,98.5 113.2,98.5 114.1,97.6 114.1,96.5 114.5,96.1 125.3,96.1 128.1,98.9 128.1,103.1 129.1,103.6 132.5,103.6 133.5,103.1 133.5,101.2 21+1.P$1
N$37
  Top 0.406: 23+1.P$2 102.55,79.35 104.2,81 105.7,81 108.3,83.6 108.3,89.8 110.4,91.9 111,91.9 112.2,93.1 112.2,95.97 22+1.P$1
N$38
  Top 0.406: 26+1.P$2 83.5,83.4 86.4,86.3 93.3,86.3 94,85.6 94,83.23 25+1.P$1
N$39
  Top 0.406: 25+1.P$2 91.05,78.05 93.9,75.2 93.9,69.71 24+1.P$1
N$40
  Top 0.406: 24+1.P$2 91.05,66.75 92.6,65.2 95.1,65.2 98,68.1 98,70.4 99.2,71.6 104.2,71.6 105.9,73.3 105.9,76.03 23+1.P$1
N$41
  Top 0.406: 7+1.P$1 137.8,45.1 119.8,45.1 117.9,47 117.9,49.7 2+1.P$2
N$42
  Top 0.406: 27+1.P$1 127.2,38.1 137.12,38.1 138.29,39.27 7+1.P$2
N$43
  Top 0.406: 9+1.P$2 116.48,89.48 114.7,87.7 114.7,86.06 8+1.P$1
N$44
  Top 0.406: 19+1.P$2 20+1.P$1
N$45
  Top 0.406: 19+2.P$1 77.79,108.41 74.6,111.6 74.6,115.63 30+2.P$2
N$46
  Top 0.406: 30+2.P$1 77.99,117.71 77,118.5 71.6,118.5 69.8,116.9 69.8,111 67.5,108.7 62.3,108.7 61.4,109.6 61.4,112.55 29+2.P$2
N$47
  Top 0.406: 29+2.P$1 64.53,117.47 61.4,120.6 28+2.P$2
N$48
  Top 0.406: 28+2.P$1 71.97,125.27 73.7,127 27+2.P$2
N$49
  Top 0.406: 2+2.P$1 83.8,139.5 80.8,139.5 4+2.P$2
N$50
  Top 0.406: 4+2.P$1 85.6,136.2 90.2,128.2 86.6,128.2 6+2.P$2
N$51
  Top 0.406: 6+2.P$1 89.75,121.45 88.3,120 88.3,119.6 85.2,116.5 85.2,112.7 0+2.P$2
N$52
  Top 0.406: 0+2.P$1 88.41,108.91 87.6,108.1 85.9,108.1 85,107.2 85,102.03 5+2.P$2
N$53
  Top 0.406: 5+2.P$1 93.09,102.01 94.4,100.7 94.4,95.99 3+2.P$2
N$54
  Top 0.406: 3+2.P$1 97.55,102.55 99.2,104.2 100.64,104.2 1+2.P$2
N$55
  Top 0.406: 1+2.P$1 103.9,106.8 101.5,109.2 97.5,109.2 96.1,110.6 96.1,113.36 8+2.P$2
N$56
  Top 0.406: 9+2.P$1 114.34,114.2 122.3,114.2 123.48,112.9 21+2.P$2
N$57
  Top 0.406: 21+2.P$1 128,114.2 136.9,114.2 138.37,112.88 22+2.P$2
N$58
  Top 0.406: 22+2.P$1 138,106.9 137.4,106.7 120.2,106.7 118.8,105.3 118.8,104.1 118.83,104.07 23+2.P$2
N$59
  Top 0.406: +.P$1 84.59,88.59 84.4,88.4 75.9,88.4 74.7,87.2 74.7,85.18 26+2.P$2
N$60
  Top 0.406: 24+2.P$1 103.59,84.19 102,82.6 99.1,82.6 96.7,85 96.7,86.8 87.3,96.2 81.9,96.2 81.5,95.8 81.5,92.71 +.P$2
N$61
  Top 0.406: 23+2.P$1 122.01,99.61 120.9,99.3 116.5,99.3 115.3,101.8 108.5,101.9 103.1,96.5 103.1,92.1 100.4,89.4 100.4,86.91 24+2.P$2
N$62
  Top 0.406: 7+2.P$1 71.51,139.51 68.9,139.5 74,148.6 74.7,149.3 74.7,149.77 2+2.P$2
N$63
  Top 0.406: 27+2.P$1 77.79,130.51 77,131.3 70.5,131.3 68.3,133.5 68.3,136.92 7+2.P$2
N$64
  Top 0.406: 8+2.P$1 100.11,114.39 108.2,114.3 109.6,112.4 109.6,112.64 9+2.P$2
N$65
  Top 0.406: 20+2.P$1 70.98,94.28 74.6,97.9 74.6,104.13 19+2.P$2
N$66
  Top 0.406: 30+3.P$2 37.12,70.52 45.7,79 49.7,79 49.8,76.25 19+3.P$1
N$67
  Top 0.406: 29+3.P$2 30.64,54.24 38.1,61.7 39.3,61.7 40.5,62.9 40.5,65.28 30+3.P$1
N$68
  Top 0.406: 28+3.P$2 18.99,48.21 20.6,46.6 31.2,46.6 33.9,49.3 33.9,50.54 29+3.P$1
N$69
  Top 0.406: 27+3.P$2 19.6,54 22.1,54 22.1,53.1 22.2,53 28+3.P$1
N$70
  Top 0.406: 4+3.P$2 54.7,96.06 54.7,91.2 52.4,88.9 52,88.9 51.98,88.88 2+3.P$1
N$71
  Top 0.406: 6+3.P$2 37.5,85.65 37.5,83.6 38.1,82.8 41.5,82.8 43.6,84.3 43.7,88.9 51.7,96 51.7,98.5 52.4,98.9 57.9,98.9 57.9,97 58.03,96.87 4+3.P$1
N$72
  Top 0.406: 0+3.P$2 40.3,95.88 40.3,90 40.73,89.57 6+3.P$1
N$73
  Top 0.406: 5+3.P$2 30.5,101.75 30.5,105.3 31.4,106.2 41.1,106.2 43.29,104.01 0+3.P$1
N$74
  Top 0.406: 3+3.P$2 26.1,87 31,87 33.7,89.7 33.7,101.53 5+3.P$1
N$75
  Top 0.406: 3+3.P$1 28.74,91.66 27.6,92.2 23.3,92.2 18.6,100.4 1+3.P$2
N$76
  Top 0.406: 1+3.P$1 22.26,102.84 21.8,103.5 16.5,103.5 8+3.P$2
N$77
  Top 0.406: 21+3.P$2 37.8,114.3 30.82,114.3 29.12,112.6 9+3.P$1
N$78
  Top 0.406: 22+3.P$2 50.9,114.3 44.49,114.3 21+3.P$1
N$79
  Top 0.406: 23+3.P$2 48.09,106.8 48.8,107.5 53.1,107.5 55.8,110.2 55.8,112.46 22+3.P$1
N$80
  Top 0.406: 26+3.P$2 64.5,76.2 61.3,79.4 61.3,82.95 25+3.P$1
N$81
  Top 0.406: 25+3.P$2 58.18,89.38 67.1,98.3 24+3.P$1
N$82
  Top 0.406: 24+3.P$2 52.59,102.01 23+3.P$1
N$83
  Top 0.406: 2+3.P$2 47.81,84.71 39.4,76.3 37.2,76.1 7+3.P$1
N$84
  Top 0.406: 7+3.P$2 26.6,65.9 28.6,65.9 27+3.P$1
N$85
  Top 0.406: 9+3.P$2 24.3,114.2 16.14,114.2 14.57,112.62 8+3.P$1
N$86
  Bottom 0.406: R2.1 54.65,97.16 arc121 59.8,36.4 74.58,36.48 U$1.P$8 77.67,40.22 P4ZD1.C 77.97,38.73 C5.2
N$87
  Bottom 0.406: R4.1 75.99,52.59 77.1,53.7 77.1,56.53 OK1.1
N$88
  Bottom 0.406: R1.1 77.91,47.84 U$1.P$5 74.58,53.22 73.4,54.4 71.4,54.4 70.2,55.6 PH1.2
N$89
  Bottom 0.406: R6.2 96.52,100.97 97.16,100.33 97.16,100.83 R5.1
N$90
  Bottom 0.406: R9.2 R7.1
N$91
  Bottom 0.406: B2.+ 94.01,86.39 R16.P$1
N$92
  Bottom 0.406: D2.A 53.7,69.64 R3.1
N$93
  Bottom 0.406: Q2.2 91.52,77.93 91.52,80.39 90.55,81.36 P4ZD2.A 86.77,84.66 91.41,89.3 B2.- | Q2.2 90.81,77.72 Q1.2 | OK1.3 74.61,62.39 75.7,61.3 79.9,61.3 80.8,60.8 80.8,53.1 81.4,52.1 94.4,52.1 97.3,55 97.3,69.8 96.7,70.4 96.7,75.4 94,78.1 92.4,78.1 91.8,77.5 91.53,77.5 Q2.2
N$94
  Bottom 0.406: 86.67,79.5 P4ZD2.C 86.32,81.7 83.9,81.7 82.89,80.69 R13.2 | 86.67,79.5 86.67,77.8 Q2.1 87.4,77.07 Q1.1 | 86.67,79.5 85,79.5 83.8,78.3 83.8,77.2 81,74.4 80.9,74.4 77.15,70.65 OK1.4
N$95
  Bottom 0.406: U$1.P$3 62,45.3 61.8,45.5 61.8,50.4 63.1,51.7 73.11,51.7 R4.2
N$97
  Top 0.406: 19+3.P$2 46.67,73.33 53.5,73.2 59.9,77 63.1,73.4 61.2,69.55 +3.1.P$1
RECDR+
  Bottom 0.406: R10.P$1 61.69,90.81 B1.+
VDD
  Bottom 0.406: 52.56,59.9 C3.+ 57.28,49.9 C1.2 55.77,46.6 58.6,46.6 60.9,42.7 U$1.P$2 | 52.56,59.9 52.56,60.26 P4ZD3.C 50.59,65.81 D2.C | PH1.1 63.66,66.56 60.6,61.4 54.06,61.4 52.56,59.9
VSS
  Bottom 0.406: B1.- 61.56,93.38 59.69,95.25 55.12,95.25 52.07,90.81 C9.- 47.2,77.41 P4ZD3.A 47.77,61.66 C3.- 46.99,53.84 46.99,50.8 50.03,46.48 C1.1 60.3,38.2 70.3,38.17 70.77,39.59 71.41,42.73 U$1.P$7 77.91,42.76 R1.2 80.28,43.88 | 80.28,43.88 81.3,44.9 81.3,47.9 79.2,50 79.2,58.2 78.5,58.9 75.7,58.9 74.6,57.8 OK1.2 | C5.1 80.87,40.02 P4ZD1.A 81.7,40.85 81.7,42.3 80.28,43.72 80.28,43.88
